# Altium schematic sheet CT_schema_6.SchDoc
size 277 x 170 mm
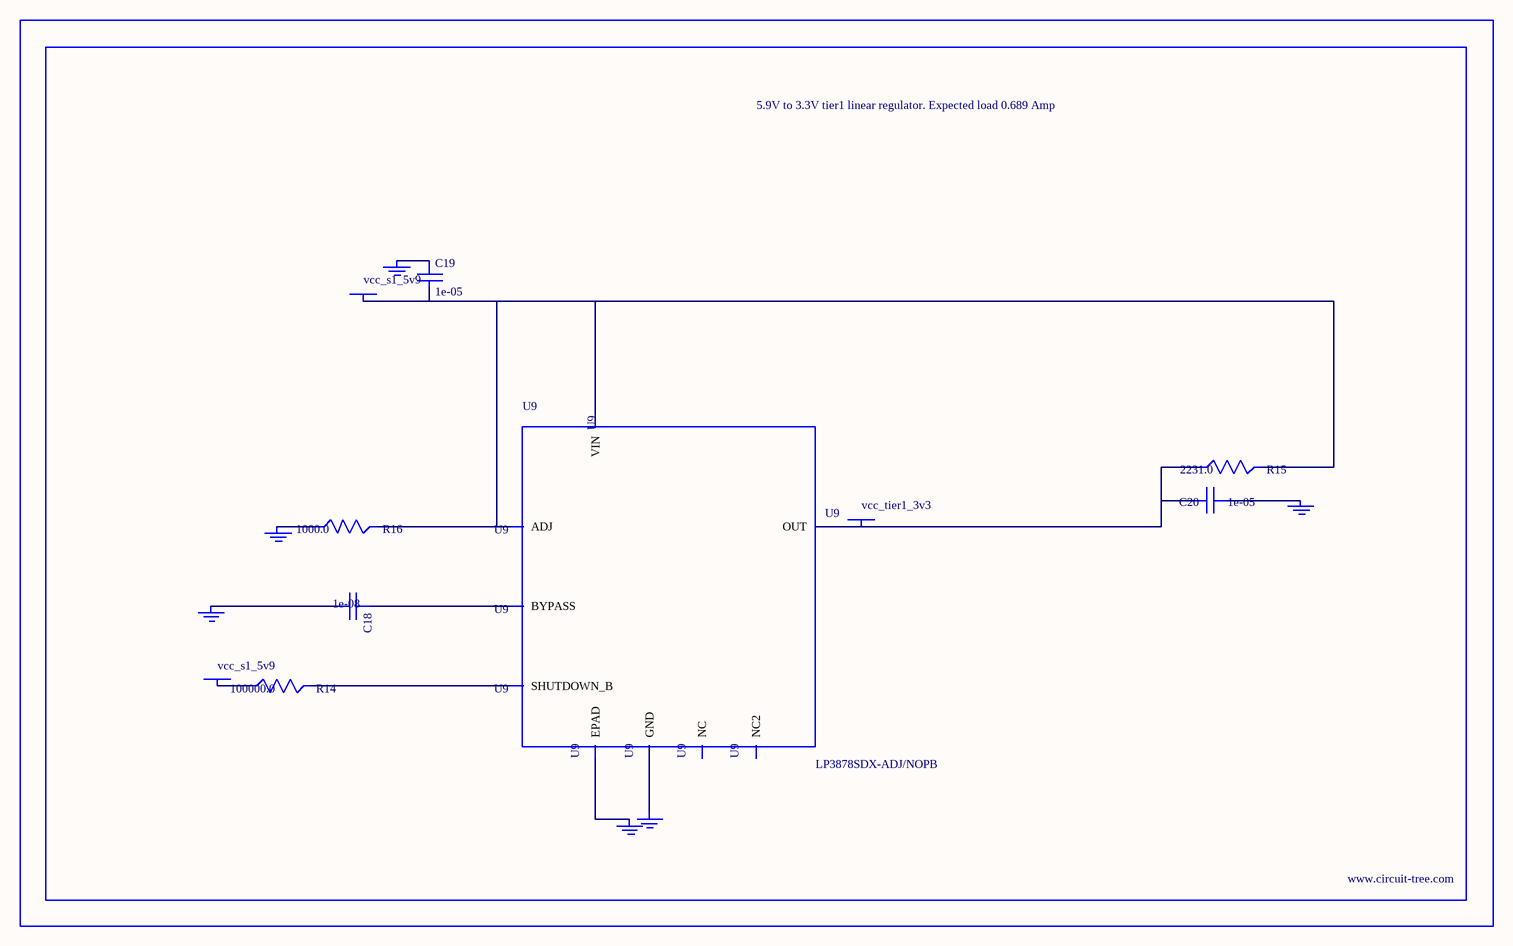
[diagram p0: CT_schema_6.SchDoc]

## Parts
BORDER5  (no value)
C18  1e-08  [C0402]
C19  1e-05  [C1206]
C20  1e-05  [C1210]
GND_INSTANCE_5_0  (no value)
GND_INSTANCE_5_1  (no value)
GND_INSTANCE_5_2  (no value)
GND_INSTANCE_5_3  (no value)
GND_INSTANCE_5_4  (no value)
GND_INSTANCE_5_5  (no value)
POWER_INSTANCE_5_0  vcc_s1_5v9
POWER_INSTANCE_5_1  vcc_s1_5v9
POWER_INSTANCE_5_2  vcc_tier1_3v3
R14  100000.0  [R0603]
R15  2231.0  [R0603]
R16  1000.0  [R0603]
U9  LP3878SDX-ADJ/NOPB  [WSON-8]

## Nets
NetC18_1: C18.1 U9.1(BYPASS)
NetC18_2: C18.2 GND_INSTANCE_5_0.0(GND)
NetC19_1: C19.1 GND_INSTANCE_5_1.0(GND)
NetC19_2: C19.2 POWER_INSTANCE_5_0.0(PWR) R15.2 R16.2 U9.4(VIN) U9.6(ADJ)
NetC20_1: C20.1 GND_INSTANCE_5_2.0(GND)
NetC20_2: C20.2 POWER_INSTANCE_5_2.0(PWR) R15.1 U9.5(OUT)
NetGND_INSTANCE_5_3_0: GND_INSTANCE_5_3.0(GND) R16.1
NetGND_INSTANCE_5_4_0: GND_INSTANCE_5_4.0(GND) U9.PAD(EPAD)
NetGND_INSTANCE_5_5_0: GND_INSTANCE_5_5.0(GND) U9.3(GND)
NetPOWER_INSTANCE_5_1_0: POWER_INSTANCE_5_1.0(PWR) R14.1
NetR14_2: R14.2 U9.8(SHUTDOWN_B)

Not connected (* = marked no-connect by the designer): U9 2(NC) 7(NC2)

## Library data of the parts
BORDER5 = BORDER_PAGE5
C18 = C0402C103K3RAC
C19 = C1206C106K3RACTU
C20 = GRM32DR61E106MA12L
GND_INSTANCE_5_0-GND_INSTANCE_5_5 = GND
POWER_INSTANCE_5_0-POWER_INSTANCE_5_2 = PWR
R14 = RC0603JR-07100KL
R15 = R15
R16 = RC0603JR-071KL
